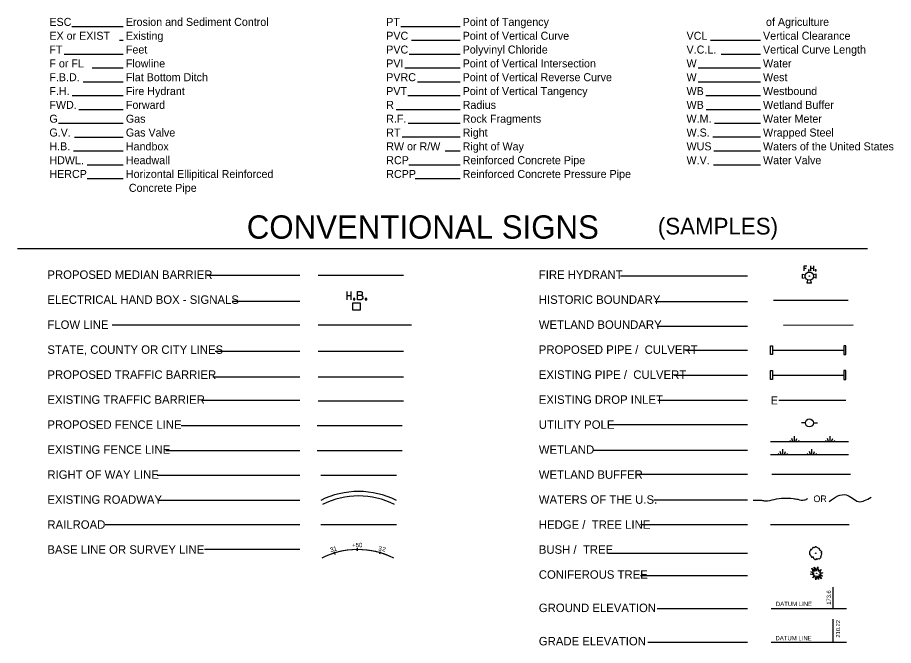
# Model space of a CAD drawing. Extents: x 1.3 to 42.5, y 0 to 21.2.
# Drawn here: x 2.66 to 15.8, y 2.08 to 11.51 of the extents above; entities that cross this region are included whole.
import ezdxf

# ---------------------------------------------------------------- set-up
doc = ezdxf.new("R2010")
doc.units = 0
for name, color, linetype in [('ANNO-LGND', 7, 'Continuous'), ('ANNO-NOTE', 7, 'Continuous'), ('USER-TEXT', 7, 'Continuous'), ('WETL-BNDY', 7, 'Continuous')]:
    doc.layers.add(name, color=color, linetype=linetype)

msp = doc.modelspace()

# ---------------------------------------------------------------- linework, layer by layer
at = {"layer": 'ANNO-LGND'}
for p, q in [((2.66, 8.038), (15.407, 8.038)), ((14.454, 7.781), (14.496, 7.781)), ((14.454, 7.706), (14.454, 7.781)), ((14.557, 7.706), (14.557, 7.781)), ((14.599, 7.706), (14.599, 7.781)), ((5.503, 7.639), (6.894, 7.639)), ((7.167, 7.639), (8.449, 7.639)), ((11.703, 7.628), (13.605, 7.628)), ((14.431, 7.625), (14.431, 7.656)), ((14.431, 7.656), (14.476, 7.646)), ((14.431, 7.625), (14.431, 7.625)), ((14.431, 7.593), (14.431, 7.625)), ((14.454, 7.744), (14.485, 7.744)), ((14.557, 7.744), (14.599, 7.744)), ((14.637, 7.656), (14.592, 7.646)), ((14.637, 7.625), (14.637, 7.656)), ((14.637, 7.625), (14.637, 7.625)), ((14.637, 7.593), (14.637, 7.625)), ((14.431, 7.593), (14.476, 7.604)), ((14.503, 7.522), (14.512, 7.567)), ((14.534, 7.522), (14.503, 7.522)), ((14.534, 7.522), (14.534, 7.522)), ((14.565, 7.522), (14.534, 7.522)), ((14.534, 7.522), (14.534, 7.522)), ((14.565, 7.522), (14.556, 7.567)), ((14.637, 7.593), (14.592, 7.604)), ((7.597, 7.393), (7.597, 7.27)), ((7.658, 7.394), (7.658, 7.332)), ((5.879, 7.251), (6.894, 7.251)), ((7.597, 7.332), (7.658, 7.332)), ((7.658, 7.332), (7.658, 7.27)), ((7.759, 7.337), (7.817, 7.338)), ((12.224, 7.243), (13.605, 7.243)), ((13.997, 7.263), (15.116, 7.263)), ((7.742, 7.167), (7.742, 7.167)), ((4.08, 6.893), (6.894, 6.893)), ((7.167, 6.893), (8.57, 6.893)), ((12.252, 6.876), (13.605, 6.876)), ((13.95, 6.515), (13.95, 6.581)), ((13.95, 6.581), (13.981, 6.581)), ((13.981, 6.581), (13.981, 6.448)), ((15.083, 6.581), (15.052, 6.581)), ((15.052, 6.581), (15.052, 6.448)), ((15.083, 6.515), (15.083, 6.581)), ((5.624, 6.499), (6.894, 6.499)), ((7.167, 6.499), (8.449, 6.499)), ((12.675, 6.515), (13.605, 6.515)), ((13.95, 6.448), (13.95, 6.515)), ((13.981, 6.448), (13.95, 6.448)), ((13.981, 6.515), (15.052, 6.515)), ((15.052, 6.548), (15.052, 6.482)), ((15.052, 6.448), (15.083, 6.448)), ((15.083, 6.448), (15.083, 6.515)), ((13.95, 6.141), (13.95, 6.207)), ((13.95, 6.207), (13.981, 6.207)), ((13.981, 6.207), (13.981, 6.074)), ((15.083, 6.207), (15.052, 6.207)), ((15.052, 6.207), (15.052, 6.074)), ((15.052, 6.174), (15.052, 6.108)), ((15.083, 6.141), (15.083, 6.207)), ((5.59, 6.114), (6.894, 6.114)), ((7.167, 6.114), (8.449, 6.114)), ((12.505, 6.141), (13.605, 6.141)), ((13.95, 6.074), (13.95, 6.141)), ((13.981, 6.074), (13.95, 6.074)), ((13.981, 6.14), (15.052, 6.141)), ((15.052, 6.074), (15.083, 6.074)), ((15.083, 6.074), (15.083, 6.141)), ((5.428, 5.762), (6.894, 5.762)), ((7.167, 5.756), (8.449, 5.756)), ((12.26, 5.766), (13.605, 5.766)), ((14.074, 5.762), (15.082, 5.762)), ((11.533, 5.397), (13.605, 5.397)), ((14.534, 5.422), (14.534, 5.422)), ((5.115, 5.385), (6.894, 5.385)), ((7.155, 5.385), (8.43, 5.385)), ((13.953, 5.144), (15.123, 5.144)), ((14.254, 5.144), (14.239, 5.161)), ((14.285, 5.144), (14.27, 5.191)), ((14.309, 5.144), (14.309, 5.224)), ((14.332, 5.144), (14.348, 5.191)), ((14.364, 5.144), (14.38, 5.161)), ((14.79, 5.144), (14.774, 5.161)), ((14.822, 5.144), (14.806, 5.191)), ((14.845, 5.144), (14.845, 5.224)), ((14.868, 5.144), (14.884, 5.191)), ((14.9, 5.144), (14.915, 5.161)), ((4.884, 5.007), (6.894, 5.007)), ((7.155, 5.01), (8.43, 5.01)), ((11.289, 5.012), (13.605, 5.012)), ((14.111, 4.948), (14.096, 4.995)), ((14.135, 4.948), (14.135, 5.029)), ((14.159, 4.948), (14.174, 4.995)), ((14.55, 4.948), (14.534, 4.995)), ((14.573, 4.948), (14.573, 5.029)), ((14.596, 4.948), (14.612, 4.995)), ((13.953, 4.948), (15.123, 4.948)), ((14.08, 4.948), (14.065, 4.966)), ((14.19, 4.948), (14.205, 4.966)), ((14.518, 4.948), (14.503, 4.966)), ((14.628, 4.948), (14.643, 4.966)), ((4.756, 4.637), (6.894, 4.637)), ((7.209, 4.637), (8.341, 4.637)), ((7.209, 4.637), (8.341, 4.637)), ((11.952, 4.651), (13.605, 4.651)), ((13.969, 4.653), (15.15, 4.653)), ((4.766, 4.261), (6.894, 4.261)), ((12.203, 4.266), (13.605, 4.266)), ((3.974, 3.9), (6.894, 3.9)), ((7.209, 3.9), (8.341, 3.9)), ((12.003, 3.898), (13.605, 3.898)), ((13.953, 3.898), (15.133, 3.897)), ((5.464, 3.526), (6.894, 3.526)), ((7.407, 3.489), (7.419, 3.45)), ((7.739, 3.522), (7.741, 3.522)), ((7.752, 3.543), (7.752, 3.502)), ((8.091, 3.459), (8.103, 3.492)), ((11.514, 3.47), (13.605, 3.47)), ((14.545, 3.154), (14.606, 3.165)), ((14.607, 3.14), (14.545, 3.154)), ((14.606, 3.165), (14.557, 3.187)), ((14.557, 3.187), (14.594, 3.183)), ((14.594, 3.183), (14.572, 3.241)), ((14.572, 3.241), (14.621, 3.192)), ((14.621, 3.192), (14.606, 3.259)), ((14.606, 3.259), (14.641, 3.205)), ((14.641, 3.205), (14.659, 3.263)), ((14.659, 3.263), (14.667, 3.197)), ((14.667, 3.197), (14.711, 3.225)), ((14.711, 3.225), (14.685, 3.176)), ((14.685, 3.176), (14.738, 3.175)), ((14.738, 3.175), (14.691, 3.156)), ((14.691, 3.156), (14.729, 3.125)), ((12.003, 3.133), (13.605, 3.133)), ((14.587, 3.098), (14.607, 3.14)), ((14.623, 3.133), (14.587, 3.098)), ((14.63, 3.07), (14.623, 3.133)), ((14.645, 3.129), (14.63, 3.07)), ((14.673, 3.071), (14.645, 3.129)), ((14.715, 3.084), (14.662, 3.12)), ((14.662, 3.12), (14.673, 3.071)), ((14.729, 3.125), (14.677, 3.141)), ((14.677, 3.141), (14.715, 3.084)), ((14.893, 2.64), (14.893, 2.956)), ((12.251, 2.64), (13.605, 2.64)), ((13.96, 2.64), (15.093, 2.64)), ((14.893, 2.134), (14.893, 2.478)), ((12.111, 2.134), (13.605, 2.134)), ((13.96, 2.134), (15.093, 2.134))]:
    msp.add_line(p, q, dxfattribs=at)
for points in [[(14.521, 7.719), (14.521, 7.706), (14.533, 7.706), (14.533, 7.719)], [(14.623, 7.718), (14.623, 7.706), (14.635, 7.706), (14.635, 7.718)], [(7.697, 7.289), (7.697, 7.268), (7.717, 7.268), (7.717, 7.289)], [(7.874, 7.289), (7.874, 7.27), (7.896, 7.27), (7.896, 7.289)], [(7.687, 7.222), (7.797, 7.222), (7.797, 7.112), (7.687, 7.112)]]:
    msp.add_lwpolyline(points, close=True, dxfattribs=at)
for points in [[(7.758, 7.27), (7.759, 7.393), (7.809, 7.393), (7.826, 7.385), (7.829, 7.369), (7.83, 7.363), (7.826, 7.349), (7.816, 7.337), (7.83, 7.324), (7.837, 7.31), (7.837, 7.294), (7.83, 7.277), (7.813, 7.271), (7.758, 7.271)], [(14.474, 5.422), (14.414, 5.422)], [(14.594, 5.422), (14.654, 5.422)], [(14.629, 3.561), (14.619, 3.561), (14.618, 3.554), (14.603, 3.55), (14.596, 3.552), (14.587, 3.553), (14.58, 3.543), (14.576, 3.534), (14.57, 3.527), (14.564, 3.525), (14.557, 3.521), (14.553, 3.523), (14.55, 3.511), (14.556, 3.507), (14.548, 3.503), (14.543, 3.498), (14.538, 3.489), (14.534, 3.478), (14.534, 3.468), (14.534, 3.459), (14.54, 3.445), (14.547, 3.447), (14.556, 3.428), (14.563, 3.418), (14.567, 3.407), (14.574, 3.408), (14.577, 3.413), (14.585, 3.408), (14.587, 3.418), (14.594, 3.399), (14.594, 3.389), (14.604, 3.384), (14.614, 3.378), (14.614, 3.374), (14.624, 3.371), (14.629, 3.369), (14.635, 3.371), (14.639, 3.377), (14.639, 3.386), (14.658, 3.376), (14.661, 3.384), (14.673, 3.387), (14.684, 3.385), (14.697, 3.395), (14.703, 3.397), (14.709, 3.408), (14.706, 3.418), (14.713, 3.433), (14.717, 3.442), (14.722, 3.451), (14.723, 3.459), (14.716, 3.465), (14.711, 3.469), (14.719, 3.482), (14.72, 3.49), (14.708, 3.505), (14.697, 3.509), (14.69, 3.514), (14.69, 3.523), (14.682, 3.538), (14.658, 3.549), (14.649, 3.553), (14.643, 3.559), (14.637, 3.561), (14.63, 3.561)]]:
    msp.add_lwpolyline(points, dxfattribs=at)
for centre, radius in [((14.534, 7.625), 0.0621), ((14.534, 7.625), 0.0031), ((14.534, 5.422), 0.06), ((14.629, 3.466), 0.00488), ((14.642, 3.167), 0.00244)]:
    msp.add_circle(centre, radius, dxfattribs=at)
for centre, major_axis, start_param, end_param in [((7.774, 2.976), (0, 1.418), 5.846227, 6.720146), ((7.774, 2.976), (0, 1.351), 5.846227, 6.720146), ((7.762, 2.171), (0, 1.351), 0.008077, 0.43696), ((7.762, 2.171), (0, 1.351), 0.018147, 0.43696), ((7.762, 2.171), (0, 1.351), 5.846227, 6.291262), ((7.762, 2.171), (0, 1.351), 5.846227, 6.280822)]:
    msp.add_ellipse(centre, major_axis=major_axis, ratio=0.9444, start_param=start_param, end_param=end_param, dxfattribs=at)
for points in [[(14.833, 4.244), (14.963, 4.327), (15.084, 4.343), (15.269, 4.243), (15.461, 4.308)], [(13.689, 4.262), (13.817, 4.262), (13.874, 4.253), (14.007, 4.274), (14.293, 4.288), (14.362, 4.276), (14.458, 4.266), (14.511, 4.29)]]:
    msp.add_spline(points, degree=3, dxfattribs=at)
at = {"layer": 'ANNO-NOTE'}
for p, q in [((3.473, 11.373), (4.245, 11.373)), ((8.406, 11.373), (9.296, 11.373)), ((4.187, 11.166), (4.245, 11.166)), ((8.567, 11.166), (9.296, 11.166)), ((13.051, 11.166), (13.799, 11.166)), ((3.359, 10.958), (4.245, 10.958)), ((8.534, 10.958), (9.296, 10.958)), ((13.21, 10.958), (13.799, 10.958)), ((3.777, 10.75), (4.245, 10.75)), ((8.468, 10.751), (9.296, 10.751)), ((12.866, 10.751), (13.799, 10.751)), ((3.644, 10.543), (4.245, 10.543)), ((8.66, 10.543), (9.296, 10.543)), ((12.866, 10.543), (13.799, 10.543)), ((3.48, 10.335), (4.245, 10.335)), ((8.511, 10.335), (9.296, 10.335)), ((12.98, 10.335), (13.799, 10.335)), ((3.582, 10.128), (4.245, 10.128)), ((8.338, 10.128), (9.296, 10.128)), ((12.984, 10.128), (13.799, 10.128)), ((3.276, 9.92), (4.245, 9.92)), ((8.516, 9.92), (9.296, 9.92)), ((13.112, 9.92), (13.799, 9.92)), ((3.515, 9.712), (4.245, 9.712)), ((8.427, 9.713), (9.296, 9.713)), ((13.085, 9.713), (13.799, 9.713)), ((3.5, 9.505), (4.245, 9.505)), ((9.073, 9.505), (9.296, 9.505)), ((13.099, 9.505), (13.799, 9.505)), ((3.706, 9.297), (4.245, 9.297)), ((8.53, 9.297), (9.296, 9.297)), ((13.097, 9.297), (13.799, 9.297)), ((3.706, 9.09), (4.245, 9.09)), ((8.622, 9.09), (9.296, 9.09))]:
    msp.add_line(p, q, dxfattribs=at)
at = {"layer": 'WETL-BNDY'}
for p, q in [((6.894, 7.639), (6.894, 7.639)), ((14.144, 6.887), (15.189, 6.894))]:
    msp.add_line(p, q, dxfattribs=at)

# ---------------------------------------------------------------- texts
at = {"layer": 'ANNO-LGND'}
for s, height, p in [('CONVENTIONAL SIGNS', 0.35, (6.098, 8.187)), ('PROPOSED MEDIAN BARRIER', 0.12712, (3.108, 7.584)), ('FIRE HYDRANT', 0.12712, (10.477, 7.584)), ('ELECTRICAL HAND BOX - SIGNALS', 0.12712, (3.108, 7.209)), ('HISTORIC BOUNDARY', 0.12712, (10.477, 7.209)), ('FLOW LINE', 0.1271, (3.108, 6.834)), ('WETLAND BOUNDARY', 0.12712, (10.477, 6.834)), ('STATE, COUNTY OR CITY LINES', 0.12712, (3.108, 6.459)), ('PROPOSED PIPE /  CULVERT', 0.12712, (10.477, 6.459)), ('PROPOSED TRAFFIC BARRIER', 0.12712, (3.108, 6.084)), ('EXISTING PIPE /  CULVERT', 0.12712, (10.477, 6.084)), ('EXISTING TRAFFIC BARRIER', 0.12712, (3.108, 5.709)), ('EXISTING DROP INLET', 0.12712, (10.477, 5.709)), ('E', 0.122, (13.954, 5.7)), ('PROPOSED FENCE LINE', 0.12712, (3.108, 5.334)), ('UTILITY POLE', 0.12712, (10.477, 5.334)), ('EXISTING FENCE LINE', 0.12712, (3.108, 4.959)), ('WETLAND', 0.1271, (10.477, 4.959)), ('RIGHT OF WAY LINE', 0.12712, (3.108, 4.584)), ('WETLAND BUFFER', 0.12712, (10.477, 4.584)), ('EXISTING ROADWAY', 0.12712, (3.108, 4.209)), ('WATERS OF THE U.S.', 0.12712, (10.477, 4.209)), ('OR', 0.1, (14.595, 4.234)), ('RAILROAD', 0.1271, (3.108, 3.834)), ('HEDGE /  TREE LINE', 0.12712, (10.477, 3.834)), ('BASE LINE OR SURVEY LINE', 0.12712, (3.108, 3.459)), ('+50', 0.066, (7.677, 3.557)), ('BUSH /  TREE', 0.12712, (10.477, 3.459)), ('CONIFEROUS TREE', 0.12712, (10.477, 3.084)), ('GROUND ELEVATION', 0.12712, (10.477, 2.584)), ('DATUM LINE', 0.0648, (14.032, 2.674)), ('GRADE ELEVATION', 0.12712, (10.477, 2.084)), ('DATUM LINE', 0.0648, (14.026, 2.16))]:
    msp.add_text(s, height=height, dxfattribs=at).set_placement(p)
for s, height, rotation, p in [('31', 0.0668, 16.3242, (7.358, 3.482)), ('3', 0.066, 348.0429, (8.066, 3.511)), ('2', 0.0662, 346.1218, (8.123, 3.502)), ('173.6', 0.0623, 90, (14.856, 2.695)), ('210.22', 0.0623, 90, (14.995, 2.201)), ('210.2', 0.0623, 90, (14.995, 2.201))]:
    msp.add_text(s, height=height, rotation=rotation, dxfattribs=at).set_placement(p)
at = {"layer": 'ANNO-NOTE'}
for s, p in [('ESC', (3.138, 11.38)), ('Erosion and Sediment Control', (4.285, 11.38)), ('PT', (8.189, 11.38)), ('Point of Tangency', (9.335, 11.38)), (' of Agriculture', (13.839, 11.38)), ('Existing', (4.285, 11.172)), ('Point of Vertical Curve', (9.335, 11.172)), ('Vertical Clearance', (13.839, 11.172)), ('EX or EXIST', (3.138, 11.172)), ('PVC', (8.189, 11.172)), ('VCL', (12.692, 11.172)), ('FT', (3.138, 10.965)), ('Feet', (4.285, 10.965)), ('PVC', (8.189, 10.965)), ('Polyvinyl Chloride', (9.335, 10.965)), ('V.C.L.', (12.692, 10.965)), ('Vertical Curve Length', (13.839, 10.965)), ('F or FL', (3.138, 10.757)), ('Flowline', (4.285, 10.757)), ('PVI', (8.189, 10.757)), ('Point of Vertical Intersection', (9.335, 10.757)), ('W', (12.692, 10.757)), ('Water', (13.839, 10.757)), ('F.B.D.', (3.138, 10.55)), ('Flat Bottom Ditch', (4.285, 10.55)), ('PVRC', (8.189, 10.55)), ('Point of Vertical Reverse Curve', (9.335, 10.55)), ('W', (12.692, 10.55)), ('West', (13.839, 10.55)), ('F.H.', (3.138, 10.342)), ('Fire Hydrant', (4.285, 10.342)), ('PVT', (8.189, 10.342)), ('Point of Vertical Tangency', (9.335, 10.342)), ('WB', (12.692, 10.342)), ('Westbound', (13.839, 10.342)), ('FWD.', (3.138, 10.135)), ('Forward', (4.285, 10.135)), ('R', (8.189, 10.135)), ('Radius', (9.335, 10.135)), ('WB', (12.692, 10.135)), ('Wetland Buffer', (13.839, 10.135)), ('G', (3.138, 9.927)), ('Gas', (4.285, 9.927)), ('R.F.', (8.189, 9.927)), ('Rock Fragments', (9.335, 9.927)), ('W.M.', (12.692, 9.927)), ('Water Meter', (13.839, 9.927)), ('G.V.', (3.138, 9.72)), ('Gas Valve', (4.285, 9.72)), ('RT', (8.189, 9.72)), ('Right', (9.335, 9.72)), ('W.S.', (12.692, 9.72)), ('Wrapped Steel', (13.839, 9.72)), ('H.B.', (3.138, 9.513)), ('Handbox', (4.285, 9.512)), ('RW or R/W', (8.189, 9.513)), ('Right of Way', (9.335, 9.512)), ('WUS', (12.692, 9.513)), ('Waters of the United States', (13.839, 9.512)), ('HDWL. ', (3.138, 9.305)), ('Headwall', (4.285, 9.305)), ('RCP', (8.189, 9.305)), ('Reinforced Concrete Pipe ', (9.335, 9.305)), ('W.V.', (12.692, 9.305)), ('Water Valve', (13.839, 9.305)), ('HERCP', (3.138, 9.098)), ('Horizontal Ellipitical Reinforced', (4.285, 9.098)), ('RCPP', (8.189, 9.098)), ('Reinforced Concrete Pressure Pipe', (9.335, 9.098)), (' Concrete Pipe ', (4.285, 8.89))]:
    msp.add_text(s, height=0.12, rotation=0.0015, dxfattribs=at).set_placement(p)
at = {"layer": 'USER-TEXT'}
msp.add_text('(SAMPLES)', height=0.25, dxfattribs=at).set_placement((12.262, 8.25))

doc.saveas('drawing.dxf')
